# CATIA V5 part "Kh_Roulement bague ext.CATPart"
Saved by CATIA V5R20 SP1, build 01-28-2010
Part number: Roulement bague ext
Bounding box of the stored display mesh (mm): x -20 to 20, y -20 to 20, z -8 to 4
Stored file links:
  G:\Khaled_CFAO_2011\SIL\SIL_GR1\tmerino\Khaled\CAD_Thinkmotion\Kh_Roulement bague ext.CATPart
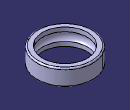
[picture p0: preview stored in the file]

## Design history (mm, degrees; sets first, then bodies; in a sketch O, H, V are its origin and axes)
Body1 (main body)
  Sketch1 on yz-plane, origin (0, 0, 0), H (0, 1, 0), V (0, 0, 1)
    line L1 (-20, -8) -> (-20, 4)
    line L2 (-20, 4) -> (-16, 4)
    line L3 (-20, -8) -> (-16, -8)
    line L4 (-16, 4) -> (-16, 1)
    line L5 (-16, -8) -> (-16, -5)
    arc A1 centre (-14.25, -2) radius 3.4731 from (-16, 1) to (-16, -5) ccw
    length L2 = 4
    length L3 = 4
    length L1 = 12
    length L4 = 3
    length L5 = 3
    distance L4 V = 16
    vertical: L1 V, L4 V, L5 V
    horizontal: L2 H, L3 H
  Shaft1: profile Sketch1, axis Sketch1.V, angle 360
  Fillet1: radius 1, on edge [face of Shaft1 from Sketch1.L1 | face of Shaft1 from Sketch1.L2]
  Fillet2: radius 1, on edge [face of Shaft1 from Sketch1.L3 | face of Shaft1 from Sketch1.L1]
